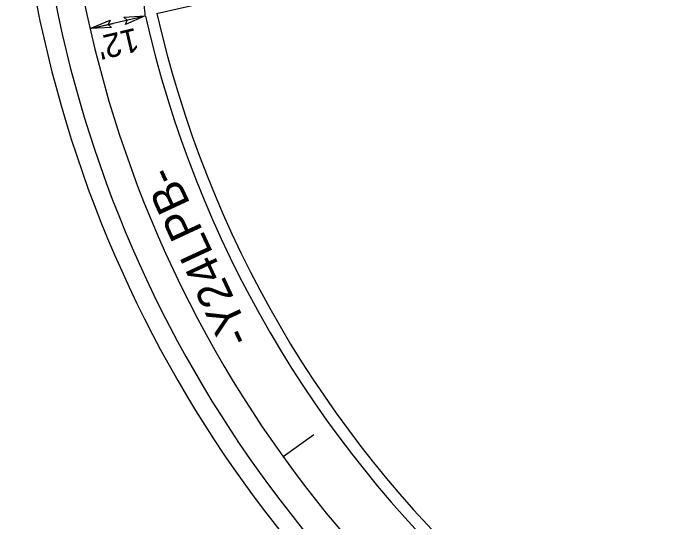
# Model space of a CAD drawing. Extents: x 2389694 to 2405615, y 547005 to 573532.
# Drawn here: x 2401845.3 to 2401987, y 570988.1 to 571095.6 of the extents above; entities that cross this region are included whole.
import ezdxf

# ---------------------------------------------------------------- set-up
doc = ezdxf.new("R2010")
doc.units = 0
for name, color, linetype in [('Prop Conc 2ft 6in Curb and Gutter', 7, 'Continuous'), ('Prop Dimension', 7, 'Continuous'), ('Prop EOT', 7, 'Continuous'), ('Prop Horizontal Alignment', 7, 'Continuous'), ('Prop Horizontal Alignment Curve and Spiral Data', 7, 'Continuous'), ('Prop Horizontal Alignment Tick Large', 7, 'Continuous'), ('Prop Horizontal Alignment Tick Small', 7, 'Continuous'), ('Prop Superelevation Label', 7, 'Continuous')]:
    doc.layers.add(name, color=color, linetype=linetype)

msp = doc.modelspace()

# ---------------------------------------------------------------- linework, layer by layer
at = {"layer": 'Prop Conc 2ft 6in Curb and Gutter'}
msp.add_arc((2402105.34, 571147.85), 235.5, 192.8217, 261.5766, dxfattribs=at)
at = {"layer": 'Prop Dimension'}
for p, q in [((2401875.62, 571095.57), (2401915.62, 571104.67)), ((2401861.57, 571092.37), (2401873.27, 571095.04))]:
    msp.add_line(p, q, dxfattribs=at)
for points in [[(2401868.72, 571094.77), (2401873.27, 571095.04), (2401869.05, 571093.23), (2401869.43, 571094.14)], [(2401866.13, 571092.62), (2401861.57, 571092.37), (2401865.8, 571094.17), (2401865.42, 571093.26)]]:
    msp.add_lwpolyline(points, close=True, dxfattribs=at)
at = {"layer": 'Prop EOT'}
for radius, start, end in [(260, 150.5977, 254.5865), (256, 150.5977, 254.6324), (238, 192.8217, 261.5766)]:
    msp.add_arc((2402105.34, 571147.85), radius, start, end, dxfattribs=at)
msp.add_spline([(2401873.27, 571095.04), (2401873.21, 571095.69), (2401873.15, 571096.33), (2401873.09, 571096.97), (2401873.03, 571097.61), (2401872.98, 571098.26), (2401872.92, 571098.9), (2401872.87, 571099.55), (2401872.82, 571100.2), (2401872.77, 571100.84), (2401872.73, 571101.49), (2401872.68, 571102.13), (2401872.64, 571102.78), (2401872.6, 571103.42), (2401872.56, 571104.06), (2401872.52, 571104.71), (2401872.48, 571105.35), (2401872.45, 571106), (2401872.42, 571106.64), (2401872.39, 571107.28), (2401872.36, 571107.92), (2401872.33, 571108.57), (2401872.31, 571109.21), (2401872.28, 571109.85), (2401872.26, 571110.5), (2401872.24, 571111.14), (2401872.22, 571111.79), (2401872.21, 571112.42), (2401872.19, 571113.07), (2401872.18, 571113.71), (2401872.17, 571114.35), (2401872.16, 571115), (2401872.15, 571115.63), (2401872.14, 571116.28), (2401872.14, 571116.91), (2401872.14, 571117.56), (2401872.14, 571118.19), (2401872.14, 571118.84), (2401872.14, 571119.48), (2401872.15, 571120.12), (2401872.15, 571120.76), (2401872.16, 571121.4), (2401872.17, 571122.04), (2401872.18, 571122.67), (2401872.19, 571123.32), (2401872.21, 571123.96), (2401872.23, 571124.59), (2401872.25, 571125.23), (2401872.27, 571125.86), (2401872.29, 571126.51), (2401872.31, 571127.14), (2401872.34, 571127.78), (2401872.36, 571128.42), (2401872.39, 571129.05), (2401872.42, 571129.69), (2401872.46, 571130.32), (2401872.49, 571130.96), (2401872.53, 571131.59), (2401872.57, 571132.23), (2401872.61, 571132.86), (2401872.65, 571133.5), (2401872.69, 571134.13), (2401872.73, 571134.76), (2401872.78, 571135.4), (2401872.83, 571136.03), (2401872.88, 571136.66), (2401872.93, 571137.29), (2401872.98, 571137.93), (2401873.04, 571138.56), (2401873.1, 571139.19), (2401873.15, 571139.82), (2401873.21, 571140.45), (2401873.28, 571141.08), (2401873.34, 571141.7), (2401873.41, 571142.34)], degree=3, dxfattribs=at)
at = {"layer": 'Prop Horizontal Alignment'}
msp.add_arc((2402105.34, 571147.85), 250, 150.5977, 261.5766, dxfattribs=at)
at = {"layer": 'Prop Horizontal Alignment Tick Large'}
msp.add_line((2401902.42, 571001.83), (2401908.91, 571006.5), dxfattribs=at)
at = {"layer": 'Prop Horizontal Alignment Tick Small'}
msp.add_line((2401861.57, 571092.37), (2401866.45, 571093.48), dxfattribs=at)

# ---------------------------------------------------------------- texts
at = {"layer": 'Prop Horizontal Alignment Curve and Spiral Data'}
msp.add_text('-Y24LPB-', height=7, rotation=114.9258, dxfattribs=at).set_placement((2401896.04, 571026.95))
msp.add_text('-Y24LPB-', height=7, rotation=114.9258, dxfattribs=at).set_placement((2401896.04, 571026.95))
at = {"layer": 'Prop Superelevation Label'}
msp.add_text("12'", height=5, rotation=193.1919, dxfattribs=at).set_placement((2401871.22, 571092.58))

doc.saveas('drawing.dxf')
